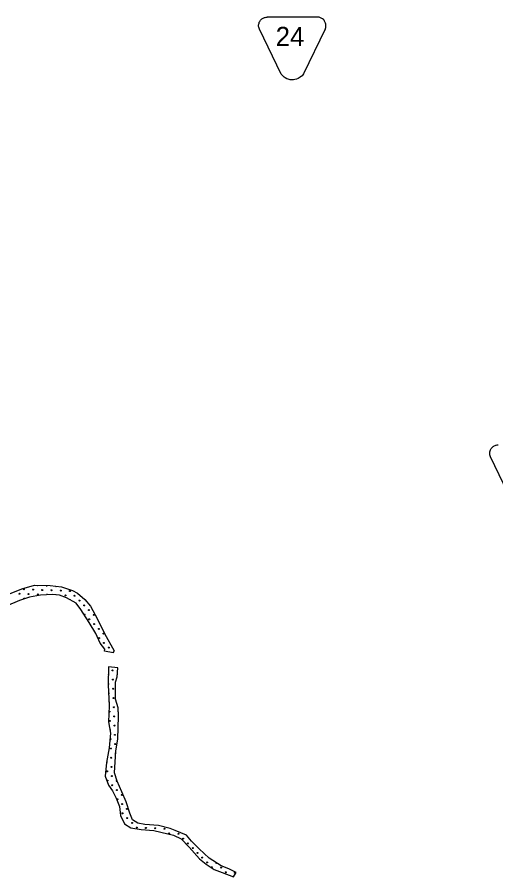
# Model space of a CAD drawing. Extents: x 1612280 to 1883141, y 560852 to 780851.
# Drawn here: x 1684509 to 1694990, y 629834 to 648648 of the extents above; entities that cross this region are included whole.
import ezdxf

# ---------------------------------------------------------------- set-up
doc = ezdxf.new("R2010")
doc.units = 0
for name, color, linetype in [('DESIGN - ROW - Easement Linework and Patterning', 7, 'Continuous'), ('DESIGN - SCRATCH - User 1', 7, 'Continuous'), ('DESIGN - TRAFFIC CONTROL PERMANENT - Pavement Marking Text', 7, 'Continuous')]:
    doc.layers.add(name, color=color, linetype=linetype)

msp = doc.modelspace()

# ---------------------------------------------------------------- linework, layer by layer
at = {"layer": 'DESIGN - ROW - Easement Linework and Patterning'}
for points in [[(1690289, 647402), (1689814, 648383), (1689804, 648410), (1689799, 648428), (1689796, 648446), (1689796, 648461), (1689796, 648479), (1689798, 648495), (1689804, 648519), (1689811, 648536), (1689819, 648552), (1689829, 648569), (1689839, 648582), (1689854, 648598), (1689869, 648610), (1689882, 648619), (1689895, 648627), (1689911, 648634), (1689927, 648640), (1689939, 648643), (1689961, 648647), (1689980, 648648)], [(1690289, 647402), (1689814, 648383), (1689804, 648410), (1689799, 648428), (1689796, 648446), (1689796, 648461), (1689796, 648479), (1689798, 648495), (1689804, 648519), (1689811, 648536), (1689819, 648552), (1689829, 648569), (1689839, 648582), (1689854, 648598), (1689869, 648610), (1689882, 648619), (1689895, 648627), (1689911, 648634), (1689927, 648640), (1689939, 648643), (1689961, 648647), (1689980, 648648)], [(1691251, 648383), (1691257, 648400), (1691265, 648424), (1691268, 648440), (1691270, 648461), (1691269, 648476), (1691267, 648494), (1691262, 648516), (1691255, 648534), (1691249, 648549), (1691240, 648564), (1691228, 648580), (1691216, 648594), (1691197, 648610), (1691182, 648620), (1691168, 648628), (1691154, 648635), (1691138, 648640), (1691118, 648645), (1691104, 648647), (1691085, 648648), (1689980, 648648)], [(1691251, 648383), (1691257, 648400), (1691265, 648424), (1691268, 648440), (1691270, 648461), (1691269, 648476), (1691267, 648494), (1691262, 648516), (1691255, 648534), (1691249, 648549), (1691240, 648564), (1691228, 648580), (1691216, 648594), (1691197, 648610), (1691182, 648620), (1691168, 648628), (1691154, 648635), (1691138, 648640), (1691118, 648645), (1691104, 648647), (1691085, 648648), (1689980, 648648)], [(1691251, 648383), (1690778, 647405), (1690763, 647385), (1690748, 647368), (1690735, 647355), (1690707, 647332), (1690685, 647318), (1690661, 647305), (1690628, 647291), (1690591, 647281), (1690559, 647277), (1690524, 647276), (1690486, 647279), (1690446, 647288), (1690410, 647302), (1690375, 647321), (1690353, 647336), (1690323, 647361), (1690289, 647402)], [(1691251, 648383), (1690778, 647405), (1690763, 647385), (1690748, 647368), (1690735, 647355), (1690707, 647332), (1690685, 647318), (1690661, 647305), (1690628, 647291), (1690591, 647281), (1690559, 647277), (1690524, 647276), (1690486, 647279), (1690446, 647288), (1690410, 647302), (1690375, 647321), (1690353, 647336), (1690323, 647361), (1690289, 647402)], [(1695349, 638043), (1694875, 639023), (1694864, 639050), (1694860, 639068), (1694857, 639086), (1694857, 639102), (1694857, 639119), (1694859, 639136), (1694865, 639159), (1694872, 639177), (1694880, 639193), (1694890, 639209), (1694900, 639223), (1694915, 639239), (1694930, 639251), (1694943, 639260), (1694955, 639267), (1694972, 639275), (1694988, 639281), (1695000, 639284), (1695022, 639287), (1695041, 639288)], [(1695349, 638043), (1694875, 639023), (1694864, 639050), (1694860, 639068), (1694857, 639086), (1694857, 639102), (1694857, 639119), (1694859, 639136), (1694865, 639159), (1694872, 639177), (1694880, 639193), (1694890, 639209), (1694900, 639223), (1694915, 639239), (1694930, 639251), (1694943, 639260), (1694955, 639267), (1694972, 639275), (1694988, 639281), (1695000, 639284), (1695022, 639287), (1695041, 639288)]]:
    msp.add_lwpolyline(points, dxfattribs=at)
at = {"layer": 'DESIGN - SCRATCH - User 1'}
for points in [[(1683675, 634117), (1683721, 634389), (1683671, 634602), (1683647, 634854), (1683609, 635060), (1683651, 635293), (1683717, 635522), (1683841, 635677), (1684035, 635871), (1684337, 636030), (1684613, 636134), (1684888, 636220), (1685229, 636208), (1685481, 636181), (1685721, 636100), (1685830, 636045), (1685989, 635902), (1686113, 635754), (1686268, 635471), (1686419, 635157), (1686629, 634781), (1686609, 634734)], [(1683675, 634117), (1683721, 634389), (1683671, 634602), (1683647, 634854), (1683609, 635060), (1683651, 635293), (1683717, 635522), (1683841, 635677), (1684035, 635871), (1684337, 636030), (1684613, 636134), (1684888, 636220), (1685229, 636208), (1685481, 636181), (1685721, 636100), (1685830, 636045), (1685989, 635902), (1686113, 635754), (1686268, 635471), (1686419, 635157), (1686629, 634781), (1686609, 634734)], [(1684775, 635951), (1684558, 635878), (1684268, 635758), (1684097, 635650), (1683954, 635498), (1683841, 635297), (1683779, 635095), (1683775, 634916), (1683857, 634738), (1683903, 634505), (1683915, 634199)], [(1684775, 635951), (1684558, 635878), (1684268, 635758), (1684097, 635650), (1683954, 635498), (1683841, 635297), (1683779, 635095), (1683775, 634916), (1683857, 634738), (1683903, 634505), (1683915, 634199)], [(1686419, 634769), (1686427, 634816), (1686326, 634944), (1686229, 635157), (1686086, 635397), (1685900, 635681), (1685799, 635820), (1685590, 635941), (1685438, 635999), (1685276, 636014), (1685016, 635999), (1684775, 635951)], [(1686419, 634769), (1686427, 634816), (1686326, 634944), (1686229, 635157), (1686086, 635397), (1685900, 635681), (1685799, 635820), (1685590, 635941), (1685438, 635999), (1685276, 636014), (1685016, 635999), (1684775, 635951)], [(1686609, 634734), (1686419, 634769)], [(1686609, 634734), (1686419, 634769)], [(1686511, 634428), (1686504, 634032), (1686522, 633574), (1686511, 633224), (1686554, 632978), (1686522, 632653), (1686468, 632338), (1686433, 632034)], [(1686511, 634428), (1686504, 634032), (1686522, 633574), (1686511, 633224), (1686554, 632978), (1686522, 632653), (1686468, 632338), (1686433, 632034)], [(1686643, 632113), (1686672, 632581), (1686711, 632853), (1686729, 633342), (1686718, 633535), (1686661, 633724), (1686665, 634096), (1686700, 634214), (1686715, 634407), (1686511, 634428)], [(1686643, 632113), (1686672, 632581), (1686711, 632853), (1686729, 633342), (1686718, 633535), (1686661, 633724), (1686665, 634096), (1686700, 634214), (1686715, 634407), (1686511, 634428)], [(1686433, 632034), (1686505, 631843), (1686594, 631715), (1686679, 631554), (1686748, 631373), (1686768, 631173), (1686859, 630996), (1686994, 630907), (1687220, 630868), (1687502, 630848), (1687653, 630812), (1687929, 630746), (1688096, 630664), (1688277, 630484), (1688500, 630224), (1688644, 630109), (1688821, 629995), (1688995, 629926), (1689244, 629834), (1689307, 629929)], [(1686433, 632034), (1686505, 631843), (1686594, 631715), (1686679, 631554), (1686748, 631373), (1686768, 631173), (1686859, 630996), (1686994, 630907), (1687220, 630868), (1687502, 630848), (1687653, 630812), (1687929, 630746), (1688096, 630664), (1688277, 630484), (1688500, 630224), (1688644, 630109), (1688821, 629995), (1688995, 629926), (1689244, 629834), (1689307, 629929)], [(1689307, 629929), (1689143, 630008), (1688975, 630077), (1688713, 630244), (1688496, 630444), (1688329, 630615), (1688214, 630746), (1687965, 630848), (1687860, 630891), (1687604, 630956), (1687306, 630976), (1687151, 631009), (1687037, 631081), (1686974, 631229), (1686895, 631478), (1686800, 631692), (1686695, 631925), (1686643, 632113)], [(1689307, 629929), (1689143, 630008), (1688975, 630077), (1688713, 630244), (1688496, 630444), (1688329, 630615), (1688214, 630746), (1687965, 630848), (1687860, 630891), (1687604, 630956), (1687306, 630976), (1687151, 631009), (1687037, 631081), (1686974, 631229), (1686895, 631478), (1686800, 631692), (1686695, 631925), (1686643, 632113)]]:
    msp.add_lwpolyline(points, dxfattribs=at)
for centre in [(1685565, 635992), (1685565, 635992), (1686530, 633449), (1686530, 633449), (1686635, 633344), (1686635, 633344)]:
    msp.add_circle(centre, 10.6, dxfattribs=at)
msp.add_arc((1685364, 635999), 10.6, 31.6624, 137.4498, dxfattribs=at)
at = {"layer": 'DESIGN - TRAFFIC CONTROL PERMANENT - Pavement Marking Text'}
for centre in [(1684654, 636126), (1684654, 636126), (1684856, 636119), (1684856, 636119), (1685057, 636111), (1685057, 636111), (1685259, 636104), (1685259, 636104), (1684557, 636029), (1684557, 636029), (1684662, 635925), (1684662, 635925), (1684759, 636022), (1684759, 636022), (1684960, 636014), (1684960, 636014), (1685461, 636097), (1685461, 636097), (1685662, 636089), (1685662, 636089), (1685767, 635985), (1685767, 635985), (1685871, 635880), (1685871, 635880), (1685976, 635775), (1685976, 635775), (1685983, 635574), (1685983, 635574), (1686080, 635671), (1686080, 635671), (1686185, 635566), (1686185, 635566), (1686088, 635469), (1686088, 635469), (1686192, 635365), (1686192, 635365), (1686297, 635260), (1686297, 635260), (1686304, 635059), (1686304, 635059), (1686401, 635156), (1686401, 635156), (1686409, 634954), (1686409, 634954), (1686513, 634850), (1686513, 634850), (1686597, 634352), (1686597, 634352), (1686605, 634151), (1686605, 634151), (1686612, 633949), (1686612, 633949), (1686620, 633747), (1686620, 633747), (1686627, 633546), (1686627, 633546), (1686538, 633247), (1686538, 633247), (1686642, 633143), (1686642, 633143), (1686650, 632941), (1686650, 632941), (1686553, 632844), (1686553, 632844), (1686657, 632739), (1686657, 632739), (1686560, 632642), (1686560, 632642), (1686567, 632441), (1686567, 632441), (1686575, 632239), (1686575, 632239), (1686478, 632142), (1686478, 632142), (1686582, 632037), (1686582, 632037), (1686485, 631940), (1686485, 631940), (1686590, 631836), (1686590, 631836), (1686694, 631731), (1686694, 631731), (1686799, 631627), (1686799, 631627), (1686702, 631530), (1686702, 631530), (1686806, 631425), (1686806, 631425), (1686814, 631223), (1686814, 631223), (1686911, 631321), (1686911, 631321), (1686918, 631119), (1686918, 631119), (1687023, 631014), (1687023, 631014), (1687127, 630910), (1687127, 630910), (1687329, 630902), (1687329, 630902), (1687531, 630895), (1687531, 630895), (1687732, 630887), (1687732, 630887), (1687837, 630783), (1687837, 630783), (1688038, 630775), (1688038, 630775), (1688143, 630671), (1688143, 630671), (1688248, 630566), (1688248, 630566), (1688352, 630462), (1688352, 630462), (1688457, 630357), (1688457, 630357), (1688561, 630253), (1688561, 630253), (1688666, 630148), (1688666, 630148), (1688770, 630044), (1688770, 630044), (1688972, 630036), (1688972, 630036), (1689076, 629932), (1689076, 629932), (1689278, 629924), (1689278, 629924)]:
    msp.add_circle(centre, 10.6, dxfattribs=at)
for centre, start, end in [((1684953, 636216), 169.2892, 6.8044), ((1685154, 636209), 166.0269, 10.0668), ((1685356, 636201), 211.9714, 315.7295), ((1685162, 636007), 6.2167, 180.621), ((1685670, 635887), 5.7764, 114.4735), ((1686618, 634745), 89.1807, 225.6074), ((1686500, 634255), 315.7379, 42.1988), ((1686702, 634248), 80.648, 270.8838), ((1686508, 634053), 250.1765, 107.7602), ((1686515, 633852), 248.5588, 115.9113), ((1686523, 633650), 250.9156, 113.5545), ((1686732, 633441), 145.3407, 221.0123), ((1686545, 633045), 264.0342, 115.685), ((1686665, 632538), 60.9047, 292.1103), ((1686470, 632344), 255.0499, 86.9609), ((1686687, 631933), 71.0702, 319.9255), ((1688867, 630141), 125.0552, 349.8772)]:
    msp.add_arc(centre, 10.6, start, end, dxfattribs=at)

# ---------------------------------------------------------------- texts
at = {"layer": 'DESIGN - ROW - Easement Linework and Patterning'}
msp.add_text('24', height=422.4, rotation=0.0012, dxfattribs=at).set_placement((1690169, 648014))
msp.add_text('24', height=422.4, rotation=0.0012, dxfattribs=at).set_placement((1690169, 648014))

doc.saveas('drawing.dxf')
